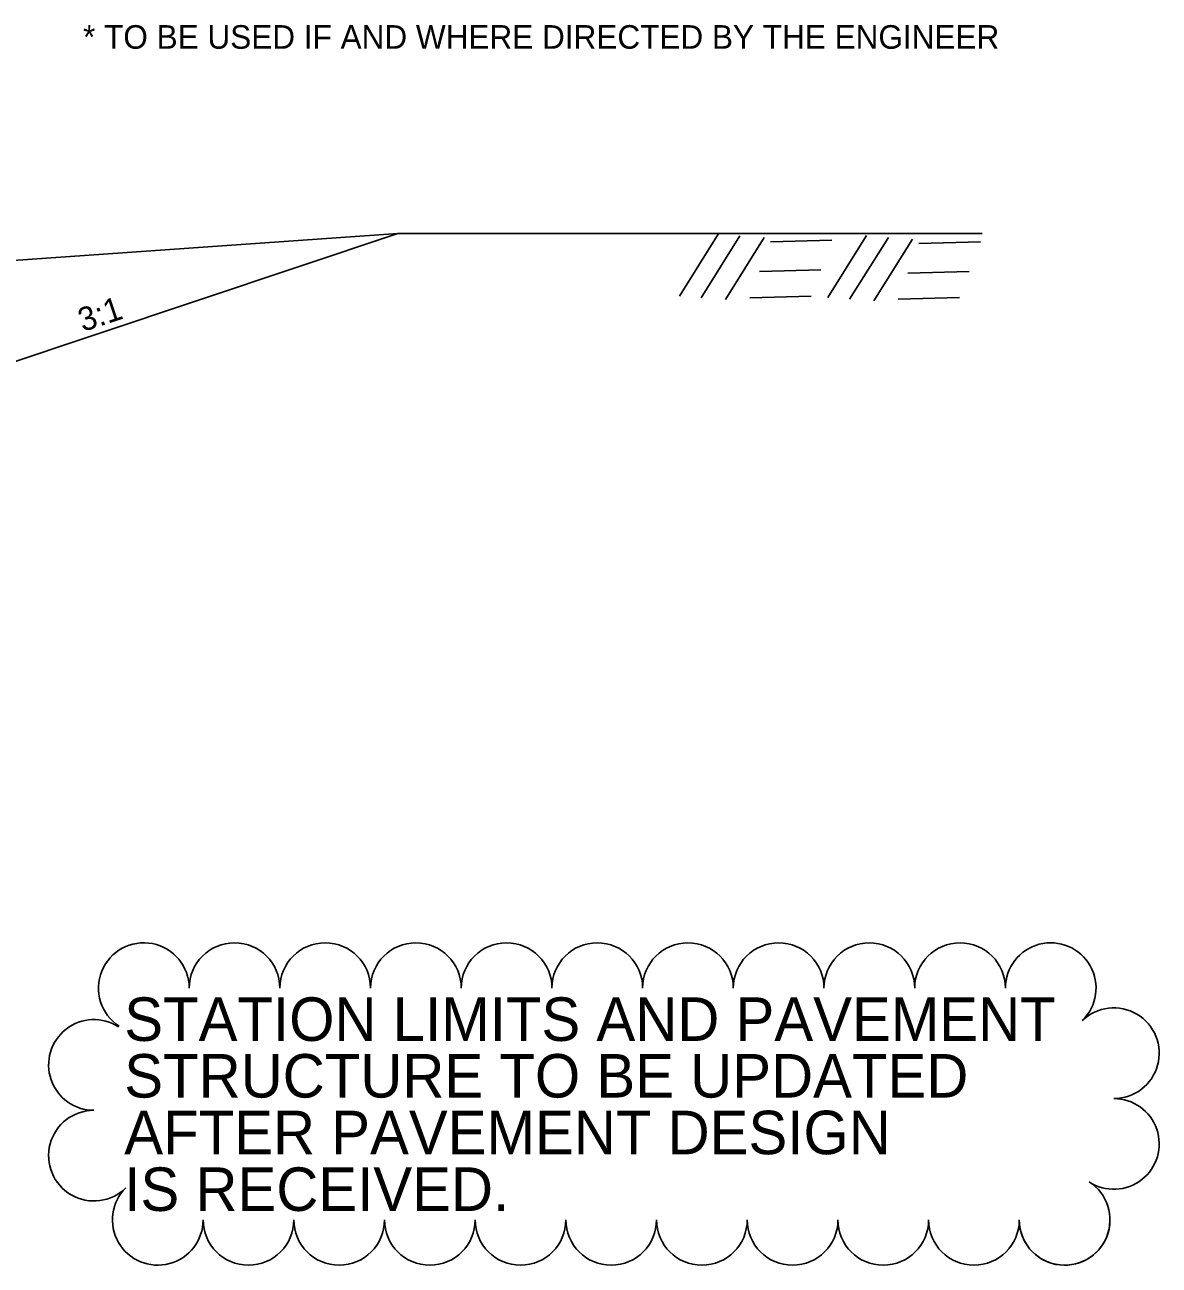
# Model space of a CAD drawing. Extents: x 1373719 to 1374161, y 379835 to 380167.
# Drawn here: x 1373818.28 to 1373849.55, y 380085.51 to 380119.71 of the extents above; entities that cross this region are included whole.
import ezdxf

# ---------------------------------------------------------------- set-up
doc = ezdxf.new("R2010")
doc.units = 0
for name, color, linetype in [('_30% NOTES', 7, 'Continuous'), ('GREEN_TXT', 7, 'Continuous'), ('Ground Hatch', 7, 'Continuous'), ('Pavement Layers', 7, 'Continuous'), ('T_Drafting', 7, 'Continuous')]:
    doc.layers.add(name, color=color, linetype=linetype)

msp = doc.modelspace()

# ---------------------------------------------------------------- linework, layer by layer
msp.add_line((1373815.66, 380109.65), (1373828.561, 380113.95))
at = {"layer": '_30% NOTES'}
for centre, start, end in [((1373821.561, 380093.152), 0, 236.9636), ((1373824.061, 380093.152), 0, 180), ((1373826.561, 380093.152), 0, 180), ((1373829.061, 380093.152), 0, 180), ((1373831.561, 380093.152), 0, 180), ((1373834.061, 380093.152), 0, 180), ((1373836.561, 380093.152), 0, 180), ((1373839.061, 380093.152), 0, 180), ((1373841.561, 380093.152), 0, 180), ((1373844.061, 380093.152), 0, 180), ((1373846.561, 380093.152), 314.1183, 180), ((1373848.302, 380091.358), 270, 134.1183), ((1373820.185, 380091.035), 56.9636, 270), ((1373848.302, 380088.858), 237.0496, 90), ((1373820.185, 380088.535), 90, 314.8317), ((1373821.945, 380086.765), 134.8317, 0), ((1373846.945, 380086.765), 180, 57.0496), ((1373824.445, 380086.765), 180, 0), ((1373826.945, 380086.765), 180, 0), ((1373829.445, 380086.765), 180, 0), ((1373831.945, 380086.765), 180, 0), ((1373834.445, 380086.765), 180, 0), ((1373836.945, 380086.765), 180, 0), ((1373839.445, 380086.765), 180, 0), ((1373841.945, 380086.765), 180, 0), ((1373844.445, 380086.765), 180, 0), ((1373846.945, 380086.765), 180, 0)]:
    msp.add_arc(centre, 1.25, start, end, dxfattribs=at)
at = {"layer": 'Ground Hatch'}
for p, q in [((1373836.326, 380112.227), (1373837.394, 380113.935)), ((1373836.926, 380112.178), (1373837.994, 380113.886)), ((1373840.418, 380112.189), (1373841.486, 380113.896)), ((1373837.596, 380112.132), (1373838.663, 380113.84)), ((1373838.834, 380113.72), (1373840.53, 380113.766)), ((1373841.018, 380112.14), (1373842.085, 380113.848)), ((1373841.688, 380112.094), (1373842.755, 380113.802)), ((1373842.926, 380113.682), (1373844.622, 380113.728)), ((1373838.529, 380112.902), (1373840.225, 380112.948)), ((1373842.621, 380112.864), (1373844.317, 380112.91)), ((1373838.262, 380112.183), (1373839.958, 380112.229)), ((1373842.354, 380112.145), (1373844.049, 380112.19))]:
    msp.add_line(p, q, dxfattribs=at)
at = {"layer": 'T_Drafting'}
msp.add_lwpolyline([(1373727.631, 380106.564), (1373744.177, 380106.487), (1373763.094, 380108.654), (1373773.229, 380112.614), (1373774.67, 380112.615), (1373784.496, 380112.903), (1373794.672, 380112.689), (1373796.247, 380112.615), (1373805.332, 380110.353), (1373813.633, 380112.909), (1373828.561, 380113.95), (1373844.667, 380113.95)], dxfattribs=at)

# ---------------------------------------------------------------- texts
at = {"layer": '_30% NOTES'}
for s, p in [('STATION LIMITS AND PAVEMENT', (1373821.021, 380091.697)), ('STRUCTURE TO BE UPDATED', (1373821.021, 380090.135)), ('AFTER PAVEMENT DESIGN', (1373821.021, 380088.573)), ('IS RECEIVED.', (1373821.021, 380087.01))]:
    msp.add_text(s, height=1.2, dxfattribs=at).set_placement(p)
at = {"layer": 'GREEN_TXT'}
msp.add_text('3:1', height=0.65, rotation=18.4782, dxfattribs=at).set_placement((1373819.88, 380111.236))
at = {"layer": 'Pavement Layers'}
msp.add_text('* TO BE USED IF AND WHERE DIRECTED BY THE ENGINEER', height=0.65, dxfattribs=at).set_placement((1373819.885, 380119.047))

doc.saveas('drawing.dxf')
